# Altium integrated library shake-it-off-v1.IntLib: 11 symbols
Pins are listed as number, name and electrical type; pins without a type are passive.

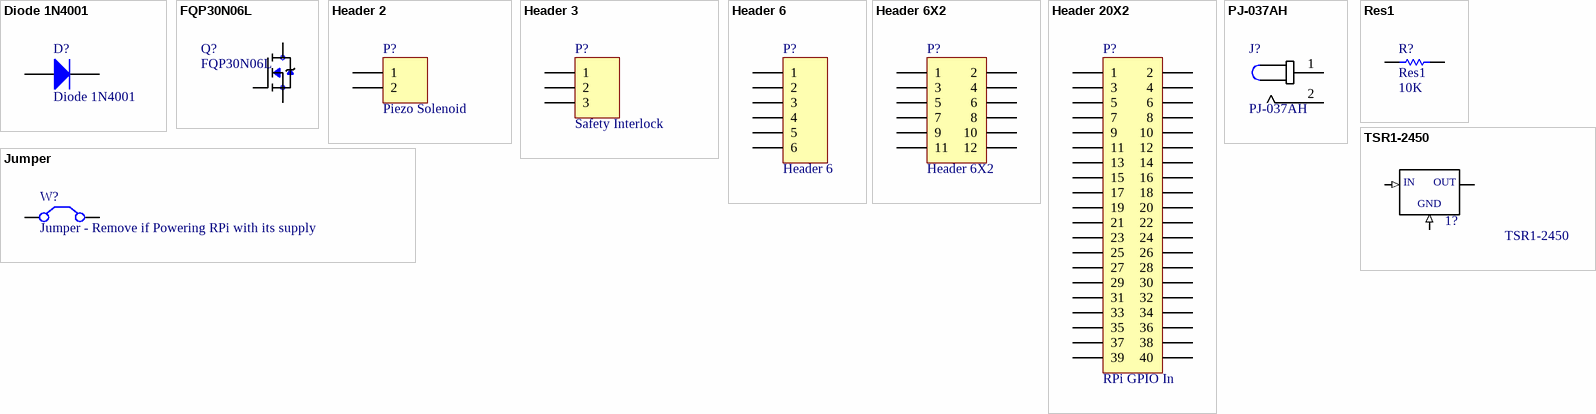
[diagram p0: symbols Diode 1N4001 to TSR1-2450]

## Diode 1N4001
designator D?
1 Amp General Purpose Rectifier
footprint DO-41 (Diode, Axial; Body 5.2 x 2.7 mm (LxDia. max), Lead Dia. 0.86 mm (max))
simulation model 1N4001 (DIODE)
signal-integrity model 1N4001
pins: 1 A, 2 K

## FQP30N06L
designator Q?
MOSFET Transistor, N Channel, 32 A, 60 V, 27 mohm, 10 V, 2.5 V; MF: ON Semiconductor
footprint *TO220V
pins: 1 G, 2 D, 3 S

## Header 2
designator P?, comment Piezo Solenoid
Header, 2-Pin
footprint HDR1X2 (Connector; Header; 2 Position)
signal-integrity model Connector
pins: 1, 2

## Header 3
designator P?, comment Safety Interlock
Header, 3-Pin
footprint HDR1X3 (Connector; Header; 3 Position)
signal-integrity model Connector
pins: 1, 2, 3

## Header 6
designator P?
Header, 6-Pin
footprint HDR1X6 (Connector; Header; 6 Position)
signal-integrity model Connector
pins: 1, 2, 3, 4, 5, 6

## Header 6X2
designator P?
Header, 6-Pin, Dual row
footprint HDR2X6 (Connector; Header; 6x2 Position)
signal-integrity model Connector
pins: 1, 2, 3, 4, 5, 6, 7, 8, 9, 10, 11, 12

## Header 20X2
designator P?, comment RPi GPIO In
Header, 20-Pin, Dual row
footprint HDR2X20 (Connector; Header; 20x2 Position)
signal-integrity model Connector
pins: 1, 2, 3, 4, 5, 6, 7, 8, 9, 10, 11, 12, 13, 14, 15, 16, 17, 18, 19, 20, 21, 22, 23, 24, 25, 26, 27, 28, 29, 30, 31, 32, 33, 34, 35, 36, 37, 38, 39, 40

## Jumper
designator W?, comment Jumper - Remove if Powering RPi with its supply
Jumper Wire
footprint RAD-0.2 (Radial Cap, Thru-Hole; 2 Leads; 0.2 in Pin Spacing)
footprint HDR1X2 (Connector; Header; 2 Position)
pins: 1 C1, 2 C2

## PJ-037AH
designator J?
2.0 mm Center Pin, 5.0 A, Right Angle, Through Hole, Dc Power Jack Connector; MF: CUI Inc.
footprint *CUI_PJ-037AH
pins: 1, 2

## Res1
designator R?  value 10K
Resistor
footprint AXIAL-0.3 (Axial Device, Thru-Hole; 2 Leads; 0.3 in Pin Spacing)
simulation model RESISTOR (Resistor)
signal-integrity model Res
footprint 0603
pins: 1, 2

## TSR1-2450
designator 1?
Converter: DC/DC; Uin: 6.5Ã·36V; 5VDC; Iout: 1A; SIP3; Eff; MF: Traco Power
footprint *TSR1-2450
pins: 1 IN (in), 2 GND (in), 3 OUT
